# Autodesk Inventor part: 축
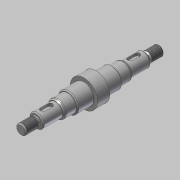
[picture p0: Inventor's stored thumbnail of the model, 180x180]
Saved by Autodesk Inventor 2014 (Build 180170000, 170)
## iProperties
Created: 2019-09
Part Number: 축
Material: 강철, 연강
Document SubType Name: Modeling
Designer: mduedu
Density: 7.86 g/cm^3
Mass: 210.278 g
Surface Area: 69.4769 cm^2
Volume: 26.7529 cm^3
Appearance: 강철
Author: mduedu
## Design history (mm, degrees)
sketch "스케치1"
  geometry: L1 (0, 0)-(15, 0); L2 (15, 0)-(15, 5); L3 (15, 5)-(0, 5); L4 (0, 5)-(0, 0); L5 (15, 0)-(34, 0); L6 (34, 0)-(34, 7); L7 (34, 7)-(15, 7); L8 (15, 7)-(15, 0); L9 (34, 0)-(46, 0); L10 (46, 0)-(46, 8.5); L11 (46, 8.5)-(34, 8.5); L12 (34, 8.5)-(34, 0); L13 (46, 0)-(62, 0); L14 (62, 10)-(46, 10); L15 (46, 10)-(46, 0); L16 (62, 10)-(62, 0); L17 (62, 0)-(68, 0); L18 (68, 0)-(68, 13.5); L19 (68, 13.5)-(62, 13.5); L20 (62, 13.5)-(62, 0)
  constraints: 40 end point, 10 parallel, 5 horizontal, 4 perpendicular, 1 vertical
  dimensions: "d2" = 15 distance of L2.end L3.end; "d3" = 19 distance of L6.end L7.end; "d8" = 16 distance of L14.start L14.end; "d9" = 10 diameter of L3 L1; "d10" = 14 diameter of L7 L5; "d11" = 17 diameter of L11 L9; "d12" = 20 diameter of L14 L13; "d73" = 12 distance of L10.end L11.end (derived); "d74" = 27 diameter of L19 L17; "d75" = 6 distance of L18.end L19.end; "d76" = 68 distance between parallel lines of L4 L18
revolve "회전1" sketch "스케치1" stored, may be unused: angle "d17" = 90 deg
revolve "회전2" stored, may be unused: angle "d22" = 90 deg
fillet "모깎기1" dims "d23" = 0.6
feature "스레드1" dims "d24" = 10, "d25" = 0
chamfer "모따기1" distance "d26" = 1; stored, may be unused: second distance "d27" = 2, angle "d28" = 45 deg
chamfer "모따기2" distance "d29" = 1; stored, may be unused: second distance "d30" = 2, angle "d31" = 45 deg
chamfer "모따기3" distance "d32" = 1.819; stored, may be unused: second distance "d33" = 2, angle "d34" = 30 deg
fillet "모깎기2" dims "d35" = 2
chamfer "모따기4" distance "d36" = 1; stored, may be unused: second distance "d37" = 2, angle "d38" = 30 deg
fillet "모깎기3" dims "d39" = 0.3
node "작업 평면1"
sketch "스케치3" dims "d51" = 12
  geometry: L1 (3, -2.5)-(-4, -2.5); L2 (-4, -2.5)-(-4, 2.5); L3 (-4, 2.5)-(3, 2.5); L4 (3, 2.5)-(3, -2.5); L5 (-9.5, 7.45)-(-9.5, -7.45) reference; 3 further points
  constraints: 8 end point, 2 midpoint, 2 parallel, 2 vertical alignment, 1 horizontal, 1 horizontal alignment, 1 perpendicular, 4 other
  dimensions: "d50" = 3 dimension on L5; "d52" = 5 distance between parallel lines of L3 L1
extrude "돌출1" cut sketch "스케치3" distance "d53" = 3; taper "d54" = 0 deg
node "솔리드1"
mirror "대칭1"
sketch "스케치2"
  geometry: L1 (0, -5)-(0, 5) reference; L2 (0, 5)-(15, 5) reference; L3 (15, 5)-(15, 7) reference; L4 (15, 7)-(34, 7) reference; L5 (34, 7)-(34, 8.5) reference; L6 (34, 8.5)-(46, 8.5) reference; L7 (46, 8.5)-(46, 10) reference; L8 (46, 10)-(62, 10) reference; L9 (62, -10)-(46, -10) reference; L10 (46, -10)-(46, -8.5) reference; L11 (46, -8.5)-(34, -8.5) reference; L12 (34, -8.5)-(34, -7) reference; L13 (34, -7)-(15, -7) reference; L14 (15, -7)-(15, -5) reference; L15 (15, -5)-(0, -5) reference; L16 (0, 0)-(74, 0); L17 (15, 5)-(12.014, 5); L18 (13.4, 4.2)-(15, 4.2); L19 (15, 4.2)-(15, 5); L20 (12.014, 5)-(13.4, 4.2); L21 (62, 10)-(62, 13.5) reference; L22 (62, 13.5)-(68, 13.5) reference; L23 (68, 13.5)-(68, -13.5) reference; L24 (68, -13.5)-(62, -13.5) reference; L25 (62, -13.5)-(62, -10) reference
  constraints: 10 end point, 1 horizontal, 1 parallel, 1 vertical
  dimensions: "d18" = 30 deg angle of L2 L20; "d19" = 8.4 diameter of L18 L16; "d21" = 2.986 distance from line of L17.end L19
node "절단 모서리 투영1"
